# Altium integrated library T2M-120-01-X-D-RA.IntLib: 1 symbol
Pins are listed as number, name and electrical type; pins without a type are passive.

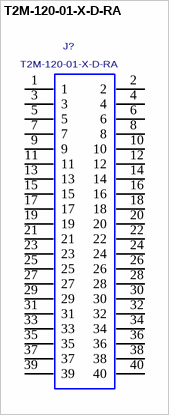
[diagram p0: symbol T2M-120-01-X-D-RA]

## T2M-120-01-X-D-RA
designator J?
2mm SHROUDED TERMINAL STRIP.; MANUFACTURER: SAMTEC
footprint T2M-120-01-X-D-RA
pins: 1, 2, 3, 4, 5, 6, 7, 8, 9, 10, 11, 12, 13, 14, 15, 16, 17, 18, 19, 20, 21, 22, 23, 24, 25, 26, 27, 28, 29, 30, 31, 32, 33, 34, 35, 36, 37, 38, 39, 40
